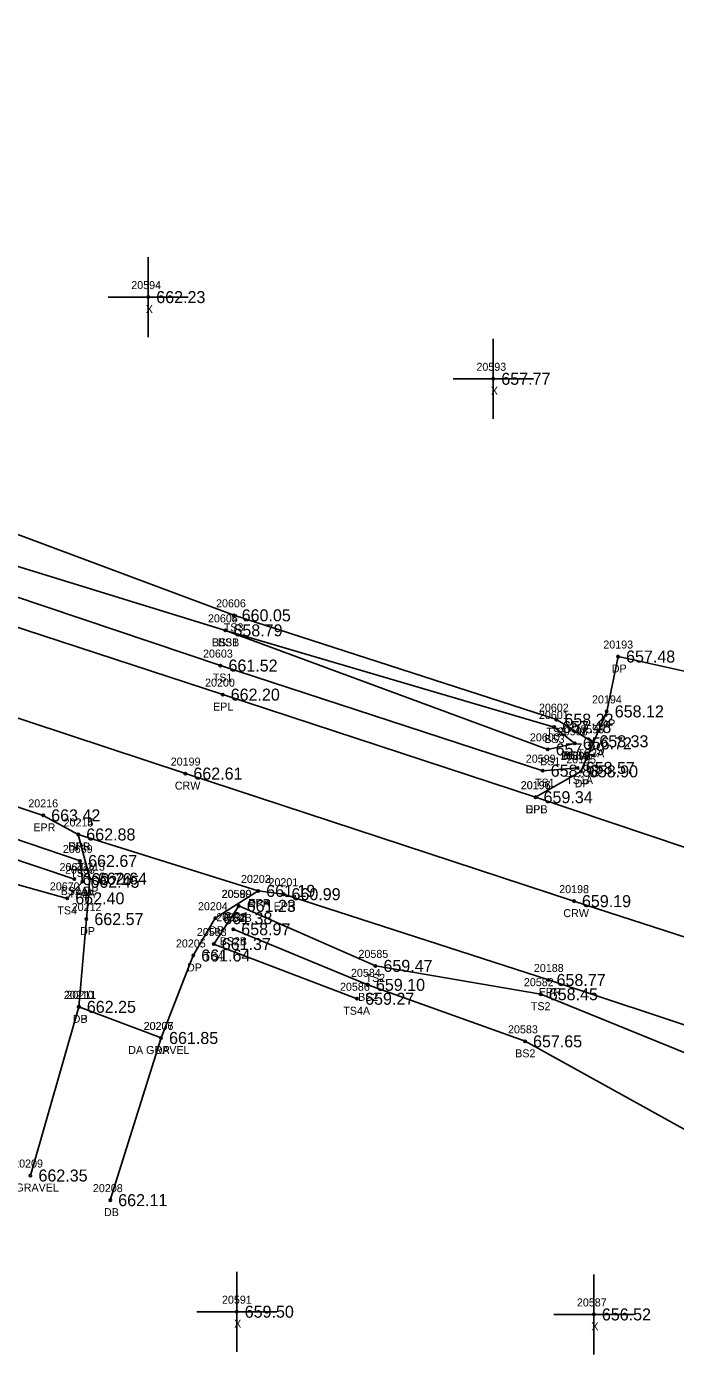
# Model space of a CAD drawing. Extents: x 1655675 to 1657082, y 1004080 to 1005193.
# Drawn here: x 1656215.6 to 1656296.6, y 1004598.6 to 1004764.5 of the extents above; entities that cross this region are included whole.
import ezdxf

# ---------------------------------------------------------------- set-up
doc = ezdxf.new("R2010")
doc.units = 0
for name, color, linetype in [('RD_DTM_BkLn1', 7, 'Continuous'), ('RD_DTM_BkLn2', 7, 'Continuous'), ('RD_DTM_BkLn_txCode', 7, 'Continuous'), ('RD_EX_Driveway', 7, 'Continuous'), ('RD_EX_Driveway_txCode', 7, 'Continuous'), ('RD_EX_Misc', 7, 'Continuous'), ('RD_EX_Misc_txCode', 7, 'Continuous'), ('RD_EX_Road', 7, 'Continuous'), ('RD_EX_Road_txCode', 7, 'Continuous'), ('RD_EX_TX_Driveway_ELEV', 7, 'Continuous'), ('RD_EX_TX_Misc_ELEV', 7, 'Continuous'), ('RD_EX_TX_Road_ELEV', 7, 'Continuous'), ('RD_HC_Survey_ELEV', 7, 'Continuous'), ('RD_HC_Survey_txCode', 7, 'Continuous'), ('RD_SMD_Locator', 7, 'Continuous')]:
    doc.layers.add(name, color=color, linetype=linetype)

msp = doc.modelspace()

# ---------------------------------------------------------------- linework, layer by layer
at = {"layer": 'RD_DTM_BkLn1'}
msp.add_lwpolyline([(1656361.94, 1004629.69), (1656332.67, 1004639.45), (1656283.94, 1004655.24), (1656235.41, 1004671.18), (1656186.64, 1004687.32), (1656138.18, 1004703.47), (1656089.58, 1004719.78), (1656041.19, 1004735.88), (1655992.79, 1004752.04), (1655944.27, 1004768.13), (1655895.76, 1004783.85), (1655847.16, 1004799.72), (1655798.63, 1004815.7), (1655750.32, 1004831.65), (1655701.73, 1004847.83)], dxfattribs=at)
at = {"layer": 'RD_DTM_BkLn2'}
for points in [[(1656222.54, 1004657.66), (1656222.26, 1004660.26), (1656181.43, 1004674.15), (1656133.46, 1004690.71), (1656084.98, 1004707.29), (1656036.97, 1004722.43), (1655988.18, 1004739.61), (1655939.2, 1004755.93), (1655936.75, 1004753.71)], [(1656222.54, 1004657.66), (1656220.66, 1004655.59), (1656178.92, 1004667.25), (1656132.32, 1004682.04), (1656132.53, 1004684.93), (1656082.65, 1004701.3), (1656035.3, 1004716.15), (1655986.64, 1004734.85), (1655937.74, 1004750.26), (1655936.75, 1004753.71)], [(1656221.55, 1004658), (1656180.42, 1004671.81), (1656132.72, 1004686.56), (1656083.54, 1004703.49), (1656035.97, 1004719.09), (1655987.33, 1004737.77), (1655937.99, 1004752.87)], [(1656286.11, 1004675.22), (1656281.75, 1004677.92), (1656241.44, 1004690.96), (1656208.2, 1004703.4), (1656189.37, 1004707.72), (1656188.6, 1004702.45)], [(1656284.05, 1004674.96), (1656280.66, 1004674.21), (1656240.41, 1004689.08), (1656206.36, 1004699.58), (1656189.68, 1004705.44)], [(1656284.42, 1004671.89), (1656280.04, 1004671.54), (1656239.79, 1004684.68), (1656204.88, 1004696.42), (1656188.6, 1004702.45)], [(1656284.05, 1004674.96), (1656281.47, 1004677), (1656240.41, 1004689.08)], [(1656256.86, 1004643.04), (1656238.95, 1004649.88), (1656242.07, 1004654.65)], [(1656357.54, 1004618.31), (1656343.66, 1004619.62), (1656328.32, 1004623.88), (1656279.8, 1004643.61), (1656259.15, 1004647.15), (1656242.07, 1004654.65)], [(1656361.72, 1004600.13), (1656341.81, 1004606.24), (1656323.95, 1004612.21), (1656277.83, 1004637.72), (1656258.21, 1004644.78), (1656241.39, 1004651.73)]]:
    msp.add_lwpolyline(points, dxfattribs=at)
at = {"layer": 'RD_EX_Driveway'}
for p, q in [((1656216.06, 1004620.95), (1656222.1, 1004642.03)), ((1656232.37, 1004638.14), (1656226.02, 1004617.87))]:
    msp.add_line(p, q, dxfattribs=at)
for points in [[(1656302.55, 1004660.37), (1656299.17, 1004668.59), (1656300.53, 1004683.36), (1656289.45, 1004685.81), (1656288.04, 1004678.95), (1656284.81, 1004671.46), (1656279.15, 1004668.23)], [(1656244.5, 1004656.52), (1656239.14, 1004653.11), (1656236.39, 1004648.45), (1656232.37, 1004638.14), (1656222.1, 1004642.03), (1656223.04, 1004653), (1656223.47, 1004658.05), (1656222.03, 1004663.57)]]:
    msp.add_lwpolyline(points, dxfattribs=at)
at = {"layer": 'RD_EX_Misc'}
for p, q in [((1656230.77, 1004725.73), (1656230.77, 1004735.73)), ((1656225.77, 1004730.73), (1656235.77, 1004730.73)), ((1656273.87, 1004715.52), (1656273.87, 1004725.52)), ((1656268.87, 1004720.52), (1656278.87, 1004720.52)), ((1656241.82, 1004598.93), (1656241.82, 1004608.93)), ((1656286.43, 1004598.59), (1656286.43, 1004608.59)), ((1656236.82, 1004603.93), (1656246.82, 1004603.93)), ((1656281.43, 1004603.59), (1656291.43, 1004603.59))]:
    msp.add_line(p, q, dxfattribs=at)
at = {"layer": 'RD_EX_Road'}
for points in [[(1656365.12, 1004639.99), (1656336.04, 1004649.34), (1656302.55, 1004660.37), (1656279.15, 1004668.23), (1656240.07, 1004681.05), (1656188.23, 1004698.03), (1656166.72, 1004705.51), (1656141.16, 1004714.06), (1656093.11, 1004730.11), (1656044.16, 1004746.75), (1655996.36, 1004762.45), (1655947.2, 1004778.68), (1655899.09, 1004794.03), (1655850.62, 1004809.99), (1655801.91, 1004826.1), (1655753.09, 1004842.31), (1655704.25, 1004858.1)], [(1656358.5, 1004619.83), (1656328.78, 1004629.48), (1656280.77, 1004645.39), (1656247.66, 1004656.11), (1656244.5, 1004656.52), (1656222.03, 1004663.57), (1656217.65, 1004665.96), (1656183.42, 1004677.32), (1656134.59, 1004693.72), (1656086.19, 1004709.75), (1656037.58, 1004726.13), (1655989.57, 1004741.99), (1655940.62, 1004757.88), (1655892.37, 1004773.61), (1655843.48, 1004789.36), (1655805.73, 1004801.4), (1655779.22, 1004810.43), (1655768.8, 1004813.1), (1655744.59, 1004822.13), (1655698.83, 1004837.65)]]:
    msp.add_lwpolyline(points, dxfattribs=at)
at = {"layer": 'RD_SMD_Locator'}
for centre in [(1656230.77, 1004730.73), (1656273.87, 1004720.52), (1656241.44, 1004690.96), (1656240.41, 1004689.08), (1656240.41, 1004689.08), (1656239.79, 1004684.68), (1656289.45, 1004685.81), (1656240.07, 1004681.05), (1656288.04, 1004678.95), (1656281.47, 1004677), (1656281.75, 1004677.92), (1656284.05, 1004674.96), (1656284.05, 1004674.96), (1656286.11, 1004675.22), (1656280.66, 1004674.21), (1656280.04, 1004671.54), (1656284.42, 1004671.89), (1656284.81, 1004671.46), (1656235.41, 1004671.18), (1656279.15, 1004668.23), (1656279.15, 1004668.23), (1656217.65, 1004665.96), (1656222.03, 1004663.57), (1656222.03, 1004663.57), (1656222.26, 1004660.26), (1656223.47, 1004658.05), (1656221.55, 1004658), (1656222.54, 1004657.66), (1656222.54, 1004657.66), (1656244.5, 1004656.52), (1656244.5, 1004656.52), (1656220.66, 1004655.59), (1656247.66, 1004656.11), (1656283.94, 1004655.24), (1656239.14, 1004653.11), (1656242.07, 1004654.65), (1656242.07, 1004654.65), (1656223.04, 1004653), (1656241.39, 1004651.73), (1656238.95, 1004649.88), (1656236.39, 1004648.45), (1656259.15, 1004647.15), (1656258.21, 1004644.78), (1656280.77, 1004645.39), (1656279.8, 1004643.61), (1656222.1, 1004642.03), (1656222.1, 1004642.03), (1656256.86, 1004643.04), (1656232.37, 1004638.14), (1656232.37, 1004638.14), (1656277.83, 1004637.72), (1656216.06, 1004620.95), (1656226.02, 1004617.87), (1656241.82, 1004603.93), (1656286.43, 1004603.59)]:
    msp.add_circle(centre, 0.15, dxfattribs=at)

# ---------------------------------------------------------------- texts
at = {"layer": 'RD_DTM_BkLn_txCode'}
for s, p in [('20606', (1656239.24, 1004691.96)), ('20604', (1656238.23, 1004690.08)), ('20605', (1656238.23, 1004690.08)), ('TS3', (1656240.2, 1004688.96)), ('BS3B', (1656238.71, 1004687.08)), ('BS1', (1656239.47, 1004687.08)), ('20603', (1656237.61, 1004685.68)), ('TS1', (1656238.83, 1004682.68)), ('20602', (1656279.57, 1004678.92)), ('20601', (1656279.57, 1004678)), ('TS3', (1656280.5, 1004675.92)), ('20597', (1656281.93, 1004675.96)), ('20598', (1656281.93, 1004675.96)), ('20595', (1656283.99, 1004676.22)), ('20600', (1656278.44, 1004675.21)), ('BS3', (1656280.24, 1004675)), ('20599', (1656277.93, 1004672.54)), ('BS1', (1656279.71, 1004672.21)), ('20596', (1656282.28, 1004672.89)), ('BS3A', (1656282.33, 1004672.96)), ('BS1A', (1656282.62, 1004672.96)), ('TS3A', (1656284.38, 1004673.22)), ('TS1', (1656279.08, 1004669.54)), ('TS1A', (1656282.97, 1004669.89)), ('20669', (1656220.1, 1004661.26)), ('20671', (1656219.69, 1004659)), ('20667', (1656220.37, 1004658.66)), ('20668', (1656220.37, 1004658.66)), ('TS2', (1656221.02, 1004658.26)), ('20670', (1656218.48, 1004656.59)), ('BS2A', (1656219.83, 1004656)), ('TS2A', (1656220.8, 1004655.66)), ('TS4A', (1656220.8, 1004655.66)), ('20590', (1656239.92, 1004655.65)), ('20589', (1656239.96, 1004655.65)), ('TS4', (1656219.42, 1004653.59)), ('20592', (1656239.27, 1004652.73)), ('TS2B', (1656240.36, 1004652.65)), ('TS4B', (1656240.36, 1004652.65)), ('20588', (1656236.84, 1004650.88)), ('BS2B', (1656239.69, 1004649.73)), ('TS4', (1656237.71, 1004647.88)), ('20585', (1656257.03, 1004648.15)), ('20584', (1656256.09, 1004645.78)), ('20586', (1656254.72, 1004644.04)), ('TS2', (1656257.91, 1004645.15)), ('20582', (1656277.69, 1004644.61)), ('BS2', (1656256.98, 1004642.78)), ('TS4A', (1656255.13, 1004641.04)), ('TS2', (1656278.56, 1004641.61)), ('20583', (1656275.71, 1004638.72)), ('BS2', (1656276.6, 1004635.72))]:
    msp.add_text(s, height=1, dxfattribs=at).set_placement(p)
at = {"layer": 'RD_EX_Driveway_txCode'}
for s, p in [('20193', (1656287.61, 1004686.81)), ('DP', (1656288.67, 1004683.81)), ('20194', (1656286.2, 1004679.95)), ('DP', (1656287.26, 1004676.95)), ('20195', (1656282.98, 1004672.46)), ('20196', (1656277.29, 1004669.23)), ('DP', (1656284.03, 1004669.46)), ('DPB', (1656277.9, 1004666.23)), ('20214', (1656220.2, 1004664.57)), ('DPB', (1656220.78, 1004661.57)), ('20213', (1656221.64, 1004659.05)), ('20203', (1656242.35, 1004657.52)), ('DP', (1656222.69, 1004656.05)), ('20212', (1656221.21, 1004654)), ('20204', (1656236.98, 1004654.11)), ('DPA', (1656243.24, 1004654.52)), ('DP', (1656222.26, 1004651)), ('DP', (1656238.36, 1004651.11)), ('20205', (1656234.23, 1004649.45)), ('DP', (1656235.61, 1004646.45)), ('20210', (1656220.23, 1004643.03)), ('20211', (1656220.55, 1004643.03)), ('DB', (1656221.33, 1004640.03)), ('DP', (1656221.33, 1004640.03)), ('20206', (1656230.19, 1004639.14)), ('20207', (1656230.21, 1004639.14)), ('DA GRAVEL', (1656228.27, 1004636.14)), ('DP', (1656231.59, 1004636.14)), ('20209', (1656213.9, 1004621.95)), ('DA GRAVEL', (1656211.95, 1004618.95)), ('20208', (1656223.86, 1004618.87)), ('DB', (1656225.24, 1004615.87))]:
    msp.add_text(s, height=1, dxfattribs=at).set_placement(p)
at = {"layer": 'RD_EX_Misc_txCode'}
for s, p in [('20594', (1656228.65, 1004731.73)), ('X', (1656230.46, 1004728.73)), ('20593', (1656271.76, 1004721.52)), ('X', (1656273.56, 1004718.52)), ('20591', (1656239.98, 1004604.93)), ('20587', (1656284.31, 1004604.59)), ('X', (1656241.5, 1004601.93)), ('X', (1656286.11, 1004601.59))]:
    msp.add_text(s, height=1, dxfattribs=at).set_placement(p)
at = {"layer": 'RD_EX_Road_txCode'}
for s, p in [('20200', (1656237.87, 1004682.05)), ('EPL', (1656238.87, 1004679.05)), ('20197', (1656277.31, 1004669.23)), ('20216', (1656215.79, 1004666.96)), ('EPL', (1656277.94, 1004666.23)), ('EPR', (1656216.42, 1004663.96)), ('20215', (1656220.2, 1004664.57)), ('EPR', (1656220.8, 1004661.57)), ('20202', (1656242.35, 1004657.52)), ('20201', (1656245.79, 1004657.11)), ('EPR', (1656243.28, 1004654.52)), ('EPR', (1656246.43, 1004654.11)), ('20188', (1656278.94, 1004646.39)), ('EPR', (1656279.55, 1004643.39))]:
    msp.add_text(s, height=1, dxfattribs=at).set_placement(p)
at = {"layer": 'RD_EX_TX_Driveway_ELEV'}
for s, p in [('657.48', (1656290.45, 1004685.06)), ('658.12', (1656289.04, 1004678.2)), ('658.90', (1656285.81, 1004670.71)), ('659.34', (1656280.15, 1004667.48)), ('662.88', (1656223.03, 1004662.82)), ('662.64', (1656224.47, 1004657.3)), ('661.19', (1656245.5, 1004655.77)), ('662.57', (1656224.04, 1004652.25)), ('661.38', (1656240.14, 1004652.36)), ('661.64', (1656237.39, 1004647.7)), ('662.25', (1656223.1, 1004641.28)), ('662.25', (1656223.1, 1004641.28)), ('661.85', (1656233.37, 1004637.39)), ('661.85', (1656233.37, 1004637.39)), ('662.35', (1656217.06, 1004620.2)), ('662.11', (1656227.02, 1004617.12))]:
    msp.add_text(s, height=1.5, dxfattribs=at).set_placement(p)
at = {"layer": 'RD_EX_TX_Misc_ELEV'}
for s, p in [('662.23', (1656231.77, 1004729.98)), ('657.77', (1656274.87, 1004719.77)), ('660.05', (1656242.44, 1004690.21)), ('658.79', (1656241.41, 1004688.33)), ('658.79', (1656241.41, 1004688.33)), ('661.52', (1656240.79, 1004683.93)), ('658.22', (1656282.75, 1004677.17)), ('657.48', (1656282.47, 1004676.25)), ('657.29', (1656281.66, 1004673.46)), ('656.72', (1656285.05, 1004674.21)), ('656.72', (1656285.05, 1004674.21)), ('658.33', (1656287.11, 1004674.47)), ('658.88', (1656281.04, 1004670.79)), ('658.57', (1656285.42, 1004671.14)), ('662.67', (1656223.26, 1004659.51)), ('660.76', (1656222.55, 1004657.25)), ('662.45', (1656223.54, 1004656.91)), ('662.45', (1656223.54, 1004656.91)), ('662.40', (1656221.66, 1004654.84)), ('661.23', (1656243.07, 1004653.9)), ('661.23', (1656243.07, 1004653.9)), ('658.97', (1656242.39, 1004650.98)), ('661.37', (1656239.95, 1004649.13)), ('659.47', (1656260.15, 1004646.4)), ('659.10', (1656259.21, 1004644.03)), ('659.27', (1656257.86, 1004642.29)), ('658.45', (1656280.8, 1004642.86)), ('657.65', (1656278.83, 1004636.97)), ('659.50', (1656242.82, 1004603.18)), ('656.52', (1656287.43, 1004602.84))]:
    msp.add_text(s, height=1.5, dxfattribs=at).set_placement(p)
at = {"layer": 'RD_EX_TX_Road_ELEV'}
for s, p in [('662.20', (1656241.07, 1004680.3)), ('659.34', (1656280.15, 1004667.48)), ('663.42', (1656218.65, 1004665.21)), ('662.88', (1656223.03, 1004662.82)), ('661.19', (1656245.5, 1004655.77)), ('660.99', (1656248.66, 1004655.36)), ('658.77', (1656281.77, 1004644.64))]:
    msp.add_text(s, height=1.5, dxfattribs=at).set_placement(p)
at = {"layer": 'RD_HC_Survey_ELEV'}
for s, p in [('662.61', (1656236.41, 1004670.43)), ('659.19', (1656284.94, 1004654.49))]:
    msp.add_text(s, height=1.5, dxfattribs=at).set_placement(p)
at = {"layer": 'RD_HC_Survey_txCode'}
for s, p in [('20199', (1656233.58, 1004672.18)), ('CRW', (1656234.09, 1004669.18)), ('20198', (1656282.1, 1004656.24)), ('CRW', (1656282.62, 1004653.24))]:
    msp.add_text(s, height=1, dxfattribs=at).set_placement(p)

doc.saveas('drawing.dxf')
